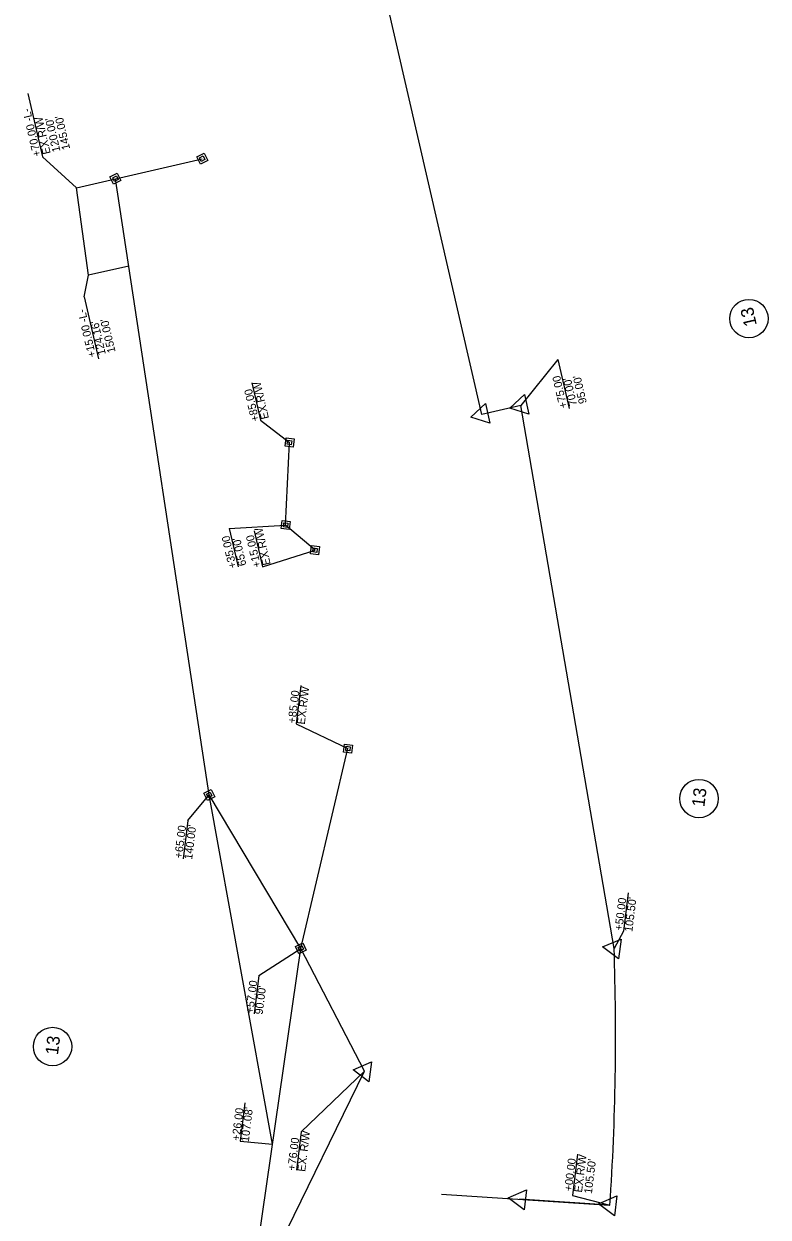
# Model space of a CAD drawing. Extents: x 474184 to 481900, y 489262 to 505659.
# Drawn here: x 481149 to 481614, y 491265 to 492010 of the extents above; entities that cross this region are included whole.
import ezdxf

# ---------------------------------------------------------------- set-up
doc = ezdxf.new("R2010")
doc.units = 0
for name, color, linetype in [('Prop Drainage Structure Drop Inlet Grate 2 Wide Slots and Sag Grates 840 22 CELL', 7, 'Continuous'), ('Prop Drainage Structure Outlet Berm Ditch 850 10 Label', 7, 'Continuous'), ('Prop Drainage Structure Outlet Generic CELL', 7, 'Continuous'), ('Prop Drainage Structure Pipe CSP 15in', 7, 'Continuous'), ('Prop Drainage Structure Pipe RCP 18in Class IV', 7, 'Continuous'), ('Prop Drainage Structure Pipe RCP 18in Class IV Label', 7, 'Continuous'), ('Prop Drainage Structure Pipe RCP 66in Class III', 7, 'Continuous'), ('Prop Drainage Structure Pipe Side Drain 15in Label', 7, 'Continuous'), ('Prop Drainage Structure Pipe Stub Out CELL', 7, 'Continuous'), ('Prop Drainage Structure Plot Symbol 50 Scale', 7, 'Continuous'), ('Prop Earthen Structure Base Ditch Lateral Detail Label', 7, 'Continuous'), ('Prop Earthen Structure False Sump CELL', 7, 'Continuous'), ('Prop Earthen Structure False Sump Label', 7, 'Continuous'), ('Sheet Clip Boundary CELL', 7, 'Continuous')]:
    doc.layers.add(name, color=color, linetype=linetype)

msp = doc.modelspace()

# ---------------------------------------------------------------- linework, layer by layer
at = {"layer": 'Prop Drainage Structure Drop Inlet Grate 2 Wide Slots and Sag Grates 840 22 CELL'}
msp.add_line((481289.91, 491208.53), (481322.37, 491432.91), dxfattribs=at)
at = {"layer": 'Prop Drainage Structure Outlet Berm Ditch 850 10 Label'}
for p, q in [((481206.53, 491913.64), (481260.75, 491926.14)), ((481265.16, 491528.69), (481206.53, 491913.64)), ((481322.37, 491432.91), (481265.16, 491528.69))]:
    msp.add_line(p, q, dxfattribs=at)
at = {"layer": 'Prop Drainage Structure Outlet Generic CELL'}
for p, q in [((481312.84, 491697.27), (481315.3, 491748.86)), ((481331.2, 491681.6), (481312.84, 491697.27)), ((481322.37, 491432.91), (481351.78, 491557.68)), ((481362.08, 491356.15), (481322.37, 491432.91))]:
    msp.add_line(p, q, dxfattribs=at)
at = {"layer": 'Prop Drainage Structure Pipe CSP 15in'}
for p, q in [((481602.2, 491826.27), (481602.2, 491826.27)), ((481571, 491526.46), (481571, 491526.46)), ((481167.28, 491371.57), (481167.28, 491371.57))]:
    msp.add_line(p, q, dxfattribs=at)
for centre in [(481602.2, 491826.27), (481571, 491526.46), (481167.28, 491371.57)]:
    msp.add_circle(centre, 12, dxfattribs=at)
at = {"layer": 'Prop Drainage Structure Pipe RCP 18in Class IV'}
for p, q in [((481260.75, 491926.14), (481260.75, 491926.14)), ((481206.53, 491913.64), (481206.53, 491913.64)), ((481459.84, 491771.92), (481459.84, 491771.92)), ((481435.48, 491766.31), (481435.48, 491766.31)), ((481315.3, 491748.86), (481315.3, 491748.86)), ((481312.84, 491697.27), (481312.84, 491697.27)), ((481331.2, 491681.6), (481331.2, 491681.6)), ((481351.78, 491557.68), (481351.78, 491557.68)), ((481265.16, 491528.69), (481265.16, 491528.69)), ((481322.37, 491432.91), (481322.37, 491432.91)), ((481517.99, 491432.89), (481517.99, 491432.89)), ((481362.08, 491356.15), (481362.08, 491356.15)), ((481458.96, 491276.22), (481458.96, 491276.22)), ((481515.41, 491272.5), (481515.41, 491272.5))]:
    msp.add_line(p, q, dxfattribs=at)
for points in [[(481464.75, 491766.64), (481452.82, 491770.3), (481461.94, 491778.82)], [(481440.39, 491761.02), (481428.46, 491764.69), (481437.58, 491773.2)], [(481520.81, 491426.25), (481510.85, 491433.77), (481522.32, 491438.66)], [(481364.9, 491349.51), (481354.93, 491357.02), (481366.41, 491361.92)], [(481461.77, 491269.58), (481451.81, 491277.09), (481463.29, 491281.98)], [(481518.23, 491265.86), (481508.27, 491273.37), (481519.74, 491278.27)]]:
    msp.add_lwpolyline(points, close=True, dxfattribs=at)
at = {"layer": 'Prop Drainage Structure Pipe RCP 18in Class IV Label'}
for points in [[(481259.58, 491922.74), (481257.35, 491927.31), (481261.92, 491929.55), (481264.16, 491924.97)], [(481260.17, 491924.44), (481259.05, 491926.73), (481261.34, 491927.84), (481262.45, 491925.56)], [(481205.36, 491910.24), (481203.13, 491914.82), (481207.7, 491917.05), (481209.93, 491912.47)], [(481205.94, 491911.94), (481204.83, 491914.23), (481207.12, 491915.34), (481208.23, 491913.06)], [(481318.13, 491751.08), (481317.51, 491746.03), (481312.46, 491746.65), (481313.08, 491751.7)], [(481316.71, 491749.97), (481316.41, 491747.45), (481313.88, 491747.76), (481314.19, 491750.28)], [(481315.67, 491699.49), (481315.05, 491694.43), (481310, 491695.05), (481310.62, 491700.1)], [(481314.25, 491698.38), (481313.95, 491695.85), (481311.42, 491696.16), (481311.73, 491698.69)], [(481334.03, 491683.82), (481333.41, 491678.76), (481328.36, 491679.38), (481328.98, 491684.43)], [(481332.61, 491682.71), (481332.3, 491680.18), (481329.78, 491680.49), (481330.09, 491683.02)], [(481354.61, 491559.9), (481354, 491554.85), (481348.94, 491555.47), (481349.56, 491560.52)], [(481353.2, 491558.79), (481352.89, 491556.27), (481350.36, 491556.58), (481350.67, 491559.1)], [(481263.99, 491525.29), (481261.76, 491529.87), (481266.33, 491532.1), (481268.57, 491527.52)], [(481264.58, 491526.99), (481263.46, 491529.28), (481265.75, 491530.4), (481266.86, 491528.11)], [(481321.19, 491429.5), (481318.96, 491434.08), (481323.54, 491436.31), (481325.77, 491431.73)], [(481321.78, 491431.2), (481320.66, 491433.49), (481322.95, 491434.61), (481324.07, 491432.32)]]:
    msp.add_lwpolyline(points, close=True, dxfattribs=at)
at = {"layer": 'Prop Drainage Structure Pipe RCP 66in Class III'}
for p, q in [((481291.74, 491786.22), (481297.15, 491762.79)), ((481277.61, 491695.07), (481283.14, 491671.11)), ((481293.24, 491693.69), (481298.43, 491671.17))]:
    msp.add_line(p, q, dxfattribs=at)
for points in [[(481297.15, 491762.79), (481315.3, 491748.86)], [(481277.61, 491695.07), (481312.84, 491697.27)], [(481298.43, 491671.17), (481331.2, 491681.6)]]:
    msp.add_lwpolyline(points, dxfattribs=at)
at = {"layer": 'Prop Drainage Structure Pipe Side Drain 15in Label'}
for p, q in [((481435.48, 491766.31), (481340.01, 492180.44)), ((481459.84, 491771.92), (481435.48, 491766.31)), ((481517.99, 491432.89), (481459.84, 491771.92)), ((481220.2, 491065.93), (481362.08, 491356.15)), ((481515.41, 491272.5), (481458.96, 491276.22))]:
    msp.add_line(p, q, dxfattribs=at)
msp.add_arc((479903.24, 491378.65), 1615.67, 356.23309, 1.92414, dxfattribs=at)
at = {"layer": 'Prop Drainage Structure Pipe Stub Out CELL'}
for p, q in [((481182.17, 491908.03), (481206.53, 491913.64)), ((481189.65, 491853.31), (481182.17, 491908.03)), ((481214.83, 491859.11), (481189.65, 491853.31)), ((481304.68, 491310.58), (481265.16, 491528.69))]:
    msp.add_line(p, q, dxfattribs=at)
at = {"layer": 'Prop Drainage Structure Plot Symbol 50 Scale'}
for p, q in [((481482.9, 491800.63), (481489.92, 491770.18)), ((481526.71, 491467.51), (481523.8, 491443.64)), ((481322.63, 491318.19), (481319.71, 491294.32)), ((481495.13, 491304.24), (481491.98, 491278.5)), ((481491.98, 491278.5), (481515.41, 491272.5))]:
    msp.add_line(p, q, dxfattribs=at)
for points in [[(481482.9, 491800.63), (481459.84, 491771.92)], [(481523.8, 491443.64), (481517.99, 491432.89)], [(481322.63, 491318.19), (481362.08, 491356.15)]]:
    msp.add_lwpolyline(points, dxfattribs=at)
at = {"layer": 'Prop Earthen Structure Base Ditch Lateral Detail Label'}
msp.add_line((481251.76, 491512.71), (481248.85, 491488.84), dxfattribs=at)
msp.add_lwpolyline([(481251.76, 491512.71), (481265.16, 491528.69)], dxfattribs=at)
at = {"layer": 'Prop Earthen Structure False Sump CELL'}
for p, q in [((481322.34, 491597.05), (481319.42, 491573.18)), ((481296.02, 491415.88), (481293.11, 491392.01))]:
    msp.add_line(p, q, dxfattribs=at)
for points in [[(481319.42, 491573.18), (481351.78, 491557.68)], [(481296.02, 491415.88), (481322.37, 491432.91)]]:
    msp.add_lwpolyline(points, dxfattribs=at)
at = {"layer": 'Prop Earthen Structure False Sump Label'}
for p, q in [((481151.92, 491966.77), (481161.01, 491927.34)), ((481187, 491839.81), (481195.91, 491801.13)), ((481287.4, 491336.31), (481284.48, 491312.44))]:
    msp.add_line(p, q, dxfattribs=at)
for points in [[(481161.01, 491927.34), (481182.17, 491908.03)], [(481187, 491839.81), (481189.65, 491853.31)], [(481284.48, 491312.44), (481304.68, 491310.58)]]:
    msp.add_lwpolyline(points, dxfattribs=at)
at = {"layer": 'Sheet Clip Boundary CELL'}
msp.add_line((481410.14, 491279.43), (481514.91, 491272.53), dxfattribs=at)

# ---------------------------------------------------------------- texts
at = {"layer": 'Prop Drainage Structure Pipe CSP 15in'}
for rotation, p in [(102.98112, (481607.21, 491822.34)), (83.03651, (481574.35, 491520.88)), (83.03651, (481170.63, 491365.99))]:
    msp.add_text('13', height=8, rotation=rotation, dxfattribs=at).set_placement(p)
at = {"layer": 'Prop Drainage Structure Pipe RCP 66in Class III'}
for s, p in [('+85.00', (481296.37, 491762.61)), ('EX.R/W', (481302.46, 491764.02)), ('+35.00', (481282.29, 491670.92)), ('+15.00', (481297.45, 491671.39)), ('EX.R/W', (481303.54, 491672.8)), ("65.00'", (481288.38, 491672.32))]:
    msp.add_text(s, height=5, rotation=102.9811, dxfattribs=at).set_placement(p)
at = {"layer": 'Prop Drainage Structure Plot Symbol 50 Scale'}
for s, rotation, p in [('+75.00', 102.98112, (481488.82, 491770.89)), ("70.00'", 102.98112, (481494.91, 491772.29)), ("95.00'", 102.98112, (481501, 491773.7)), ('+50.00', 83.03651, (481523.18, 491443.72)), ("105.50'", 83.03651, (481529.38, 491442.96)), ('EX. R/W', 83.03651, (481325.06, 491293.15)), ('+76.00', 83.03651, (481318.85, 491293.91)), ('EX.R/W', 83.03651, (481497.91, 491280.19)), ('+00.00', 83.03651, (481491.71, 491280.95)), ("105.50'", 83.03651, (481504.11, 491279.43))]:
    msp.add_text(s, height=5, rotation=rotation, dxfattribs=at).set_placement(p)
at = {"layer": 'Prop Earthen Structure Base Ditch Lateral Detail Label'}
for s, p in [('+65.00', (481248.23, 491488.92)), ("140.00'", (481254.43, 491488.16))]:
    msp.add_text(s, height=5, rotation=83.03651, dxfattribs=at).set_placement(p)
at = {"layer": 'Prop Earthen Structure False Sump CELL'}
for s, p in [('+85.00', (481319.02, 491573.23)), ('EX.R/W', (481324.78, 491572.52)), ('+57.00', (481292.71, 491392.06)), ("90.00'", (481298.47, 491391.36))]:
    msp.add_text(s, height=5, rotation=83.03651, dxfattribs=at).set_placement(p)
at = {"layer": 'Prop Earthen Structure False Sump Label'}
for s, rotation, p in [('+70.00 -L-', 102.98112, (481160.05, 491928.09)), ('EX.R/W', 102.98112, (481166.14, 491929.5)), ("120.00'", 102.98112, (481172.23, 491930.9)), ("145.00'", 102.98112, (481178.32, 491932.3)), ('+15.00 -L-', 102.98112, (481194.49, 491802.68)), ("124.16'", 102.98112, (481200.59, 491804.08)), ("150.00'", 102.98112, (481206.68, 491805.49)), ('+26.00', 83.03651, (481284.09, 491312.49)), ("107.08'", 83.03651, (481289.84, 491311.79))]:
    msp.add_text(s, height=5, rotation=rotation, dxfattribs=at).set_placement(p)

doc.saveas('drawing.dxf')
